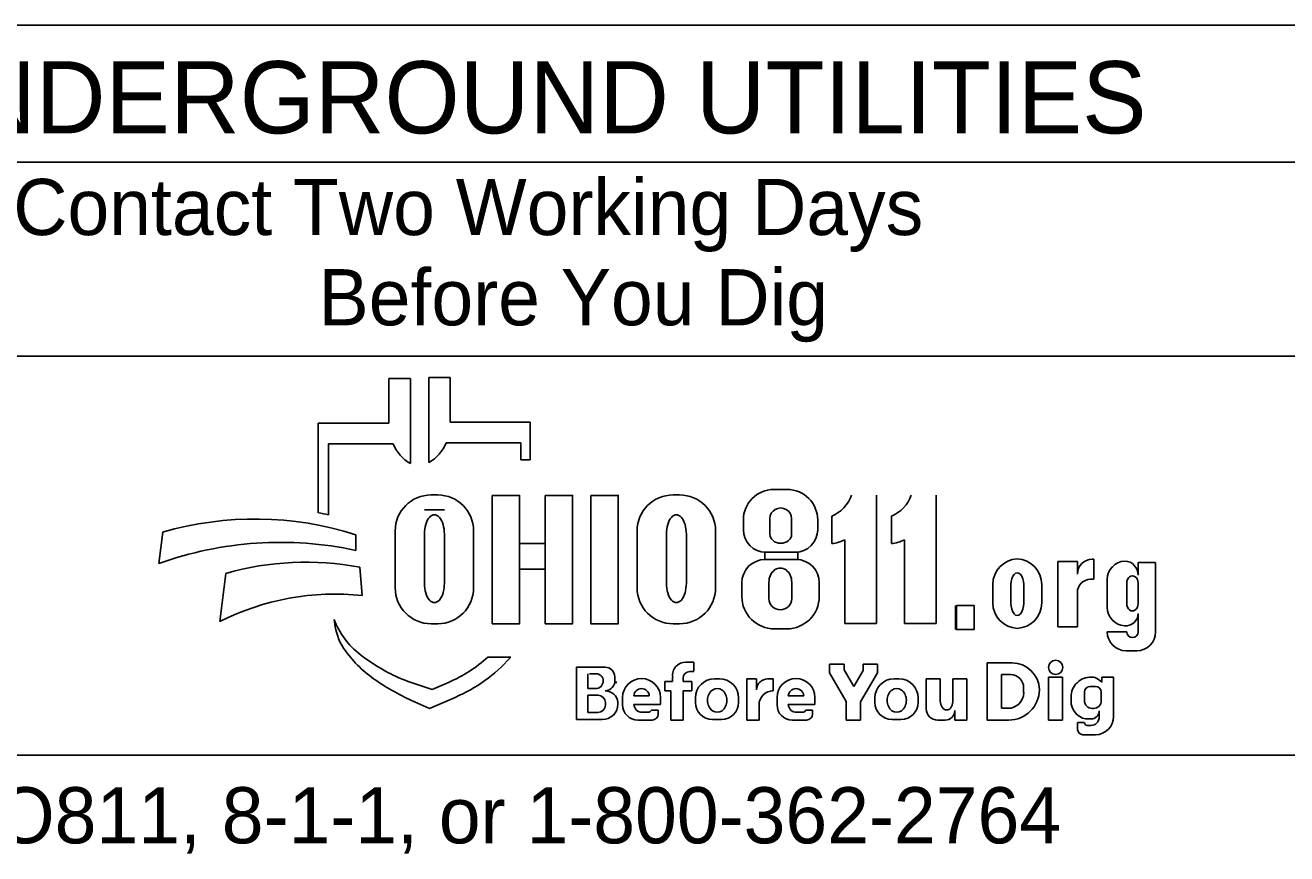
# Model space of a CAD drawing. Extents: x -15 to 405, y -40 to 87.
# Drawn here: x 3.368 to 7.346, y 2.789 to 5.402 of the extents above; entities that cross this region are included whole.
import ezdxf

# ---------------------------------------------------------------- set-up
doc = ezdxf.new("R2010")
doc.units = 0
doc.layers.add('GM_X_Adjacent_County', color=7, linetype='Continuous')
doc.layers.add('GM_X_Township', color=7, linetype='Continuous')

msp = doc.modelspace()

# ---------------------------------------------------------------- linework, layer by layer
at = {"layer": 'GM_X_Township'}
for p, q in [((8.1759, 5.4017), (2.7997, 5.4017)), ((2.7997, 4.9696), (8.1759, 4.9696)), ((2.7997, 4.3581), (8.1759, 4.3581)), ((4.515, 4.1468), (4.515, 4.2879)), ((4.515, 4.2879), (4.5829, 4.2879)), ((4.5829, 4.2879), (4.5829, 4.0196)), ((4.6407, 4.0225), (4.6407, 4.2908)), ((4.6407, 4.2908), (4.7085, 4.2908)), ((4.7085, 4.2908), (4.7085, 4.1498)), ((4.2924, 3.8636), (4.2924, 4.1468)), ((4.2924, 4.1468), (4.515, 4.1468)), ((4.7085, 4.1498), (4.9606, 4.1498)), ((4.9606, 4.1498), (4.9606, 4.0311)), ((4.3244, 4.0818), (4.3244, 3.858)), ((4.5282, 4.0818), (4.3244, 4.0818)), ((4.9311, 4.0847), (4.6953, 4.0847)), ((4.9311, 4.0311), (4.9311, 4.0847)), ((4.9606, 4.0311), (4.9311, 4.0311)), ((5.7289, 3.9379), (5.7703, 3.9379)), ((4.6479, 3.9202), (4.6688, 3.9202)), ((5.4107, 3.9202), (5.4316, 3.9202)), ((6.0522, 3.9196), (6.0522, 3.5148)), ((6.2405, 3.9196), (6.2405, 3.5148)), ((4.6899, 3.8733), (4.6269, 3.8733)), ((5.6324, 3.8106), (5.6324, 3.8413)), ((5.7161, 3.7962), (5.7161, 3.8459)), ((5.7846, 3.8459), (5.7846, 3.7962)), ((5.8668, 3.8413), (5.8668, 3.8106)), ((5.911, 3.7669), (5.911, 3.8532)), ((6.0993, 3.7669), (6.0993, 3.8532)), ((3.7898, 3.7038), (3.8017, 3.8027)), ((4.4105, 3.7945), (4.4105, 3.7453)), ((4.5347, 3.6273), (4.5347, 3.807)), ((4.6269, 3.6418), (4.6269, 3.7965)), ((4.6899, 3.7965), (4.6899, 3.6418)), ((4.782, 3.807), (4.782, 3.6273)), ((5.2975, 3.6273), (5.2975, 3.807)), ((5.3897, 3.6418), (5.3897, 3.7965)), ((5.4527, 3.7965), (5.4527, 3.6418)), ((5.5448, 3.807), (5.5448, 3.6273)), ((5.9519, 3.5148), (5.9519, 3.7787)), ((6.1402, 3.5148), (6.1402, 3.7787)), ((5.796, 3.7398), (5.7032, 3.7398)), ((5.7009, 3.7166), (5.7987, 3.7166)), ((6.6855, 3.7107), (6.6237, 3.7107)), ((6.6237, 3.7107), (6.6237, 3.5046)), ((6.6855, 3.6709), (6.6855, 3.7107)), ((6.7369, 3.7173), (6.7319, 3.7173)), ((6.7369, 3.6542), (6.7369, 3.7173)), ((6.8772, 3.6676), (6.8772, 3.7068)), ((6.8772, 3.7068), (6.9323, 3.7068)), ((6.9323, 3.7068), (6.9323, 3.4881)), ((3.9818, 3.521), (4.0004, 3.673)), ((4.4231, 3.6925), (4.431, 3.6027)), ((5.6277, 3.6003), (5.6277, 3.6434)), ((5.713, 3.5928), (5.713, 3.6445)), ((5.785, 3.6445), (5.785, 3.5928)), ((5.8719, 3.6434), (5.8719, 3.6003)), ((6.4188, 3.5803), (6.4188, 3.6377)), ((6.4757, 3.5793), (6.4757, 3.6377)), ((6.5164, 3.6377), (6.5164, 3.5793)), ((6.5733, 3.6377), (6.5733, 3.5803)), ((6.7272, 3.6542), (6.7369, 3.6542)), ((6.7799, 3.5658), (6.7799, 3.6539)), ((6.841, 3.5776), (6.841, 3.6421)), ((6.8772, 3.6421), (6.8772, 3.5776)), ((6.6855, 3.5046), (6.6855, 3.6125)), ((6.3012, 3.5718), (6.3012, 3.4958)), ((6.8772, 3.4881), (6.8772, 3.5468)), ((4.3458, 3.5047), (4.3419, 3.5274)), ((4.6688, 3.5142), (4.6479, 3.5142)), ((5.4316, 3.5142), (5.4107, 3.5142)), ((6.0522, 3.5148), (5.9519, 3.5148)), ((6.2405, 3.5148), (6.1402, 3.5148)), ((6.6237, 3.5046), (6.6855, 3.5046)), ((5.7695, 3.4979), (5.7301, 3.4979)), ((6.7799, 3.4881), (6.841, 3.4881)), ((6.8731, 3.4289), (6.839, 3.4289)), ((4.8269, 3.4087), (4.8995, 3.4087)), ((5.4516, 3.3932), (5.4762, 3.3932)), ((5.4762, 3.3932), (5.4762, 3.3642)), ((5.9044, 3.3862), (5.9498, 3.3862)), ((5.9044, 3.359), (5.9044, 3.3862)), ((5.9498, 3.3862), (5.9498, 3.369)), ((6.0097, 3.367), (6.0097, 3.3862)), ((6.0097, 3.3862), (6.055, 3.3862)), ((6.055, 3.3862), (6.055, 3.359)), ((6.4009, 3.3907), (6.4797, 3.3907)), ((6.4009, 3.2102), (6.4009, 3.3907)), ((5.1068, 3.2117), (5.1068, 3.3771)), ((5.1068, 3.3771), (5.1968, 3.3771)), ((5.1422, 3.3094), (5.1422, 3.3561)), ((5.174, 3.3561), (5.1471, 3.3561)), ((5.2269, 3.347), (5.2269, 3.337)), ((5.4095, 3.332), (5.4095, 3.3452)), ((5.4425, 3.3427), (5.4425, 3.332)), ((5.4762, 3.3635), (5.4634, 3.3635)), ((5.9567, 3.2693), (5.9044, 3.359)), ((5.9498, 3.369), (5.9803, 3.3166)), ((5.9803, 3.3166), (6.0097, 3.367)), ((6.055, 3.359), (6.0017, 3.2675)), ((6.4464, 3.2474), (6.4464, 3.3537)), ((6.4464, 3.3537), (6.4748, 3.3537)), ((6.594, 3.3456), (6.639, 3.3456)), ((6.594, 3.2102), (6.594, 3.3456)), ((6.639, 3.3456), (6.639, 3.2102)), ((6.7631, 3.3461), (6.7995, 3.3461)), ((6.7631, 3.3301), (6.7631, 3.3461)), ((6.7631, 3.3461), (6.7995, 3.3461)), ((6.7995, 3.3461), (6.7995, 3.2214)), ((4.5758, 3.3323), (4.651, 3.3064)), ((4.651, 3.3064), (4.7029, 3.3289)), ((5.1667, 3.3094), (5.1422, 3.3094)), ((5.3851, 3.303), (5.3851, 3.332)), ((5.3851, 3.332), (5.4095, 3.332)), ((5.4039, 3.303), (5.3851, 3.303)), ((5.4039, 3.2102), (5.4039, 3.303)), ((5.4425, 3.332), (5.4698, 3.332)), ((5.4698, 3.303), (5.4425, 3.303)), ((5.4425, 3.303), (5.4425, 3.2102)), ((5.4698, 3.332), (5.4698, 3.303)), ((5.5417, 3.3403), (5.557, 3.3403)), ((5.6432, 3.2102), (5.6432, 3.3401)), ((5.6432, 3.3401), (5.6743, 3.3401)), ((5.6743, 3.3401), (5.6743, 3.3061)), ((5.7087, 3.3401), (5.7263, 3.3401)), ((5.7263, 3.3401), (5.7263, 3.3026)), ((6.1077, 3.3403), (6.123, 3.3403)), ((6.2091, 3.3403), (6.253, 3.3403)), ((6.2091, 3.246), (6.2091, 3.3403)), ((6.253, 3.3403), (6.253, 3.2704)), ((6.2927, 3.2682), (6.2927, 3.3403)), ((6.2927, 3.3403), (6.3367, 3.3403)), ((6.3367, 3.3403), (6.3367, 3.2102)), ((6.5161, 3.3124), (6.5161, 3.2973)), ((6.7263, 3.3166), (6.7425, 3.3166)), ((6.7523, 3.3386), (6.7631, 3.3301)), ((4.6434, 3.2469), (4.5961, 3.2677)), ((4.7234, 3.2817), (4.6434, 3.2469)), ((5.1422, 3.2342), (5.1422, 3.2885)), ((5.1422, 3.2885), (5.1745, 3.2885)), ((5.1974, 3.2655), (5.1974, 3.2575)), ((5.2371, 3.2619), (5.2371, 3.2614)), ((5.2517, 3.2582), (5.2517, 3.2815)), ((5.3359, 3.2865), (5.2872, 3.2865)), ((5.3713, 3.2815), (5.3713, 3.2591)), ((5.4812, 3.2662), (5.4812, 3.2799)), ((5.6175, 3.2799), (5.6175, 3.2662)), ((5.7386, 3.2582), (5.7386, 3.2815)), ((5.8228, 3.2865), (5.7741, 3.2865)), ((5.8582, 3.2815), (5.8582, 3.2591)), ((5.9567, 3.2102), (5.9567, 3.2693)), ((6.0017, 3.2675), (6.0017, 3.2102)), ((6.0472, 3.2662), (6.0472, 3.2799)), ((6.1835, 3.2799), (6.1835, 3.2662)), ((6.6655, 3.2702), (6.6655, 3.283)), ((6.7078, 3.2712), (6.7078, 3.2981)), ((6.761, 3.2981), (6.761, 3.2712)), ((5.1741, 3.2342), (5.1422, 3.2342)), ((5.3713, 3.2591), (5.2872, 3.2591)), ((5.3137, 3.2348), (5.3316, 3.2348)), ((5.3424, 3.2418), (5.3638, 3.2418)), ((5.3638, 3.2418), (5.3638, 3.2294)), ((5.6818, 3.2584), (5.6818, 3.2102)), ((5.8582, 3.2591), (5.7742, 3.2591)), ((5.8006, 3.2348), (5.8185, 3.2348)), ((5.8293, 3.2418), (5.8507, 3.2418)), ((5.8507, 3.2418), (5.8507, 3.2294)), ((6.2992, 3.2102), (6.2992, 3.2406)), ((6.4662, 3.2474), (6.4464, 3.2474)), ((6.7365, 3.2468), (6.7323, 3.2468)), ((6.7545, 3.2201), (6.7545, 3.2395)), ((5.1873, 3.2117), (5.1068, 3.2117)), ((5.3445, 3.2102), (5.2997, 3.2102)), ((5.4425, 3.2102), (5.4039, 3.2102)), ((5.5634, 3.2121), (5.5353, 3.2121)), ((5.6818, 3.2102), (5.6432, 3.2102)), ((5.8314, 3.2102), (5.7866, 3.2102)), ((6.0017, 3.2102), (5.9567, 3.2102)), ((6.1294, 3.2121), (6.1013, 3.2121)), ((6.2688, 3.2102), (6.245, 3.2102)), ((6.3367, 3.2102), (6.2992, 3.2102)), ((6.4687, 3.2102), (6.4009, 3.2102)), ((6.639, 3.2102), (6.594, 3.2102)), ((6.6864, 3.1806), (6.6864, 3.2022)), ((6.6864, 3.2022), (6.7078, 3.2022)), ((6.7288, 3.2137), (6.7114, 3.2137)), ((6.7165, 3.1933), (6.7277, 3.1933)), ((6.7422, 3.1641), (6.703, 3.1641)), ((8.1759, 3.0999), (2.7997, 3.0999))]:
    msp.add_line(p, q, dxfattribs=at)
for points in [[(4.8407, 3.9188), (4.9267, 3.9188), (4.9267, 3.5141), (4.8407, 3.5141)], [(5.0078, 3.9188), (5.0938, 3.9188), (5.0938, 3.5141), (5.0078, 3.5141)], [(5.1512, 3.9188), (5.2382, 3.9188), (5.2382, 3.5141), (5.1512, 3.5141)], [(4.9267, 3.7672), (5.0078, 3.7672), (5.0078, 3.6862), (4.9267, 3.6862)], [(5.7005, 3.7398), (5.8038, 3.7398), (5.8038, 3.7164), (5.7005, 3.7164)], [(6.3043, 3.5718), (6.3601, 3.5718), (6.3601, 3.4958), (6.3043, 3.4958)]]:
    msp.add_lwpolyline(points, close=True, dxfattribs=at)
msp.add_circle((6.617, 3.3764), 0.0224, dxfattribs=at)
for centre, radius, start, end in [((4.6438, 4.1283), 0.1246, 201.9296, 240.7469), ((4.5798, 4.1312), 0.1246, 299.2531, 338.0704), ((5.7289, 3.8413), 0.0965, 90, 180), ((5.7703, 3.8413), 0.0965, 0, 90), ((4.6479, 3.807), 0.1132, 90, 180), ((4.6688, 3.807), 0.1132, 0, 90), ((5.4107, 3.807), 0.1132, 90, 180), ((5.4316, 3.807), 0.1132, 0, 90), ((5.868, 3.9565), 0.1119, 292.5572, 340.7355), ((6.0563, 3.9565), 0.1119, 292.5572, 340.7355), ((4.1304, 2.8403), 1.0361, 79.2074, 81.0007), ((4.0927, 2.8083), 1.0361, 72.1402, 106.3144), ((5.7032, 3.8106), 0.0708, 180, 270), ((5.796, 3.8106), 0.0708, 270, 0), ((5.9009, 3.8784), 0.1119, 275.1733, 297.0931), ((6.0892, 3.8784), 0.1119, 275.1733, 297.0931), ((4.1725, 2.6424), 1.1283, 77.8238, 109.8274), ((4.2533, 2.782), 0.9262, 79.44, 105.8467), ((5.7009, 3.6434), 0.0732, 90, 180), ((5.7987, 3.6434), 0.0732, 0, 90), ((6.4997, 3.6377), 0.0809, 92.5886, 180), ((6.4924, 3.6377), 0.0809, 0, 87.4114), ((6.7319, 3.6709), 0.0464, 90, 180), ((6.8379, 3.6539), 0.0581, 92.6865, 180), ((6.8328, 3.6676), 0.0444, 0, 86.9262), ((4.6479, 3.6273), 0.1132, 180, 270), ((4.6688, 3.6273), 0.1132, 270, 0), ((5.4107, 3.6273), 0.1132, 180, 270), ((5.4316, 3.6273), 0.1132, 270, 0), ((6.7272, 3.6125), 0.0417, 90, 180), ((4.3445, 2.8032), 0.8042, 83.8248, 116.8021), ((5.7301, 3.6003), 0.1024, 180, 270), ((5.7695, 3.6003), 0.1024, 270, 0), ((6.4997, 3.5803), 0.0809, 180, 267.4114), ((6.4924, 3.5803), 0.0809, 272.5886, 0), ((6.8384, 3.5658), 0.0586, 180, 265.7132), ((6.8377, 3.5468), 0.0395, 264.7825, 0), ((4.579, 3.6186), 0.254, 201.0457, 232.5314), ((4.5245, 3.5352), 0.1813, 189.6817, 216.0884), ((6.839, 3.4881), 0.0592, 180, 270), ((6.8731, 3.4881), 0.0592, 270, 0), ((4.6936, 3.6584), 0.3906, 216.0884, 235.7167), ((4.8225, 3.9364), 0.6544, 232.5314, 241.794), ((4.5215, 3.747), 0.4557, 293.4582, 312.0712), ((4.5215, 3.747), 0.5072, 293.4582, 317.8286), ((5.4516, 3.3508), 0.0424, 90, 187.5187), ((6.4797, 3.3044), 0.0863, 0.9944, 90), ((4.7148, 3.7355), 0.4264, 241.794, 250.9821), ((5.1691, 3.3347), 0.0214, 357.8325, 90), ((5.1968, 3.347), 0.0301, 0, 90), ((5.3115, 3.2815), 0.0598, 0, 180), ((5.4634, 3.3427), 0.0208, 90, 180), ((5.7984, 3.2815), 0.0598, 0, 180), ((6.4748, 3.3124), 0.0413, 0, 90), ((6.7286, 3.283), 0.0631, 89.0934, 180), ((6.7304, 3.3103), 0.0358, 52.1415, 91.2046), ((4.9043, 3.9674), 0.7645, 235.7167, 246.2325), ((5.1667, 3.3331), 0.0237, 270, 2.0582), ((5.1963, 3.3334), 0.0308, 270, 6.6529), ((5.1965, 3.2621), 0.0406, 4.0748, 90), ((5.2097, 3.3316), 0.0222, 347.4023, 0), ((5.3115, 3.2853), 0.0244, 2.9632, 177.0368), ((5.5417, 3.2799), 0.0605, 90, 180), ((5.557, 3.2799), 0.0605, 0, 90), ((5.7083, 3.3061), 0.034, 89.2449, 180), ((5.726, 3.2584), 0.0442, 89.6033, 180), ((5.7985, 3.2853), 0.0244, 2.9632, 177.0368), ((6.1077, 3.2799), 0.0605, 90, 180), ((6.123, 3.2799), 0.0605, 0, 90), ((6.4687, 3.3075), 0.0973, 270, 359.0635), ((6.7263, 3.2981), 0.0185, 90, 180), ((6.7425, 3.2981), 0.0185, 0, 90), ((5.1745, 3.2655), 0.0229, 0, 90), ((5.1873, 3.2614), 0.0498, 270, 0), ((5.1954, 3.2619), 0.0417, 0, 11.7502), ((5.5353, 3.2662), 0.0541, 180, 270), ((5.5634, 3.2662), 0.0541, 270, 0), ((6.1013, 3.2662), 0.0541, 180, 270), ((6.1294, 3.2662), 0.0541, 270, 0), ((6.4662, 3.2973), 0.05, 270, 0), ((6.7232, 3.2702), 0.0577, 180, 258.2203), ((6.7323, 3.2712), 0.0244, 180, 270), ((6.7365, 3.2712), 0.0244, 270, 0), ((5.1741, 3.2575), 0.0233, 270, 0), ((5.2997, 3.2582), 0.048, 180, 270), ((5.3137, 3.2614), 0.0266, 184.827, 270), ((5.3316, 3.2467), 0.0119, 270, 335.9979), ((5.3445, 3.2294), 0.0193, 270, 0), ((5.7866, 3.2582), 0.048, 180, 270), ((5.8006, 3.2614), 0.0266, 184.827, 270), ((5.8185, 3.2467), 0.0119, 270, 335.9979), ((5.8314, 3.2294), 0.0193, 270, 0), ((6.245, 3.246), 0.0359, 180, 270), ((6.2688, 3.2406), 0.0304, 270, 0), ((6.7288, 3.2394), 0.0257, 270, 0), ((6.7165, 3.2019), 0.00863, 180, 270), ((6.7277, 3.2201), 0.0268, 270, 0), ((6.7422, 3.2214), 0.0573, 270, 0), ((6.703, 3.1806), 0.0166, 180, 270)]:
    msp.add_arc(centre, radius, start, end, dxfattribs=at)
for centre, major_axis, ratio, start_param, end_param in [((5.7503, 3.8459), (0.0343, 0), 0.969373, 0, 3.141593), ((4.6584, 3.7965), (0, 0.0612), 0.514403, 4.712389, 7.853982), ((5.4212, 3.7965), (0, 0.0612), 0.514403, 4.712389, 7.853982), ((5.7503, 3.7962), (0.0343, 0), 0.818453, 3.141593, 6.283185), ((5.749, 3.6445), (0, 0.0453), 0.794529, 4.712389, 7.853982), ((6.4961, 3.6377), (0, 0.0368), 0.553236, 4.712389, 7.853982), ((6.8591, 3.6421), (0, 0.0233), 0.777179, 4.712389, 7.853982), ((4.6584, 3.6418), (0, 0.0612), 0.514403, 1.570796, 4.712389), ((5.4212, 3.6418), (0, 0.0612), 0.514403, 1.570796, 4.712389), ((5.749, 3.5928), (0.036, 0), 0.959837, 3.141593, 6.283185), ((6.4961, 3.5793), (0, 0.039), 0.522014, 1.570796, 4.712389), ((6.8591, 3.5776), (0, 0.0233), 0.777179, 1.570796, 4.712389), ((6.8591, 3.4881), (0.0181, 0), 0.959012, 3.141593, 6.283185), ((5.55, 3.273), (0, 0.0366), 0.832186, 4.712389, 7.853982), ((6.1159, 3.273), (0, 0.0366), 0.832186, 4.712389, 7.853982), ((5.55, 3.273), (0, 0.0382), 0.797287, 1.570796, 4.712389), ((6.1159, 3.273), (0, 0.0382), 0.797287, 1.570796, 4.712389), ((6.2729, 3.2713), (-0.0014, 0.0292), 0.679042, 1.570796, 4.575961)]:
    msp.add_ellipse(centre, major_axis=major_axis, ratio=ratio, start_param=start_param, end_param=end_param, dxfattribs=at)

# ---------------------------------------------------------------- texts
at = {"layer": 'GM_X_Adjacent_County'}
for s, height, p in [('UNDERGROUND UTILITIES', 0.2277, (2.9618, 5.0606)), ('Contact Two Working Days', 0.1771, (3.3305, 4.7399)), ('Before You Dig', 0.1771, (4.2934, 4.4553)), ('OHIO811, 8-1-1, or 1-800-362-2764', 0.1771, (2.8559, 2.8215))]:
    msp.add_text(s, height=height, dxfattribs=at).set_placement(p)

doc.saveas('drawing.dxf')
